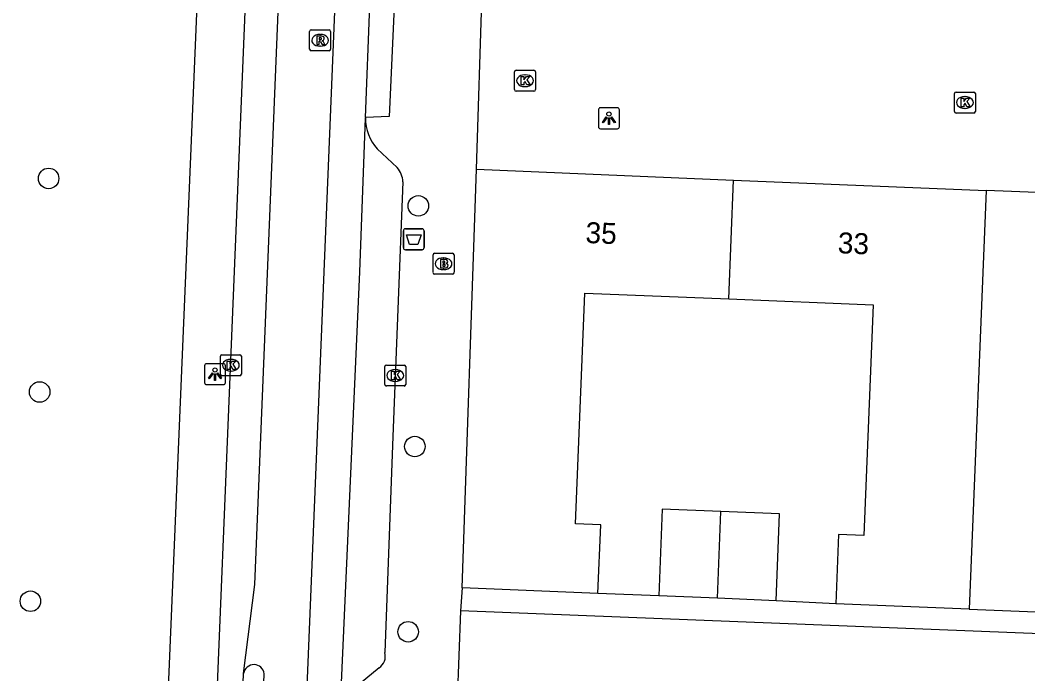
# Model space of a CAD drawing. Extents: x 160787 to 161428, y 386828 to 387483.
# Drawn here: x 161290.73 to 161338.8, y 387141.15 to 387172.31 of the extents above; entities that cross this region are included whole.
import ezdxf

# ---------------------------------------------------------------- set-up
doc = ezdxf.new("R2010")
doc.units = 0
for name, color, linetype in [('IMGEO_Afvalbak', 7, 'Continuous'), ('IMGEO_Boom', 7, 'Continuous'), ('IMGEO_Brandkraan', 7, 'Continuous'), ('IMGEO_Kolk', 7, 'Continuous'), ('IMGEO_Lichtpunt', 7, 'Continuous'), ('IMGEO_Pand', 7, 'Continuous'), ('IMGEO_Pand_nummerreeks', 7, 'Continuous'), ('IMGEO_Rijbaan_lokaal_gesloten', 7, 'Continuous'), ('IMGEO_Rijbaan_lokaal_open', 7, 'Continuous'), ('IMGEO_Rioolput', 7, 'Continuous'), ('IMGEO_Voetpad_open', 7, 'Continuous')]:
    doc.layers.add(name, color=color, linetype=linetype)

msp = doc.modelspace()

# ---------------------------------------------------------------- linework, layer by layer
at = {"layer": 'IMGEO_Afvalbak'}
for p, q in [((161309.114, 387162.368), (161309.904, 387162.368)), ((161309.904, 387162.368), (161309.114, 387162.368)), ((161309.014, 387161.468), (161309.014, 387162.268)), ((161309.014, 387162.268), (161309.014, 387161.468)), ((161310.004, 387162.268), (161310.004, 387161.468)), ((161310.004, 387161.468), (161310.004, 387162.268)), ((161309.904, 387161.368), (161309.114, 387161.368)), ((161309.114, 387161.368), (161309.904, 387161.368))]:
    msp.add_line(p, q, dxfattribs=at)
msp.add_lwpolyline([(161309.157, 387162.082), (161309.861, 387162.082), (161309.712, 387161.612), (161309.306, 387161.612), (161309.157, 387162.082)], dxfattribs=at)
for centre, start, end in [((161309.114, 387162.268), 90, 180), ((161309.114, 387162.268), 90, 180), ((161309.904, 387162.268), 0, 90), ((161309.904, 387162.268), 360, 90), ((161309.114, 387161.468), 180, 270), ((161309.114, 387161.468), 180, 270), ((161309.904, 387161.468), 270, 0), ((161309.904, 387161.468), 270, 0)]:
    msp.add_arc(centre, 0.1, start, end, dxfattribs=at)
at = {"layer": 'IMGEO_Boom'}
for centre in [(161292.092, 387164.766), (161309.728, 387163.458), (161291.664, 387154.586), (161309.563, 387151.986), (161291.224, 387144.609), (161309.243, 387143.153)]:
    msp.add_circle(centre, 0.489, dxfattribs=at)
at = {"layer": 'IMGEO_Brandkraan'}
for p, q in [((161310.43, 387160.274), (161310.43, 387161.126)), ((161310.505, 387161.2), (161311.357, 387161.2)), ((161310.918, 387160.98), (161310.943, 387160.98)), ((161311.431, 387161.126), (161311.431, 387160.274)), ((161310.941, 387160.42), (161310.916, 387160.42)), ((161311.357, 387160.2), (161310.505, 387160.2))]:
    msp.add_line(p, q, dxfattribs=at)
for points in [[(161310.43, 387160.274), (161310.43, 387161.126)], [(161310.505, 387161.2), (161311.357, 387161.2)], [(161310.778, 387160.9), (161310.778, 387160.5), (161310.991, 387160.5)], [(161311.009, 387160.9), (161310.778, 387160.9)], [(161311.431, 387161.126), (161311.431, 387160.274)], [(161310.957, 387160.819), (161310.903, 387160.819), (161310.903, 387160.743)], [(161310.903, 387160.743), (161310.956, 387160.743)], [(161310.965, 387160.667), (161310.903, 387160.667), (161310.903, 387160.586)], [(161310.903, 387160.586), (161310.965, 387160.586)], [(161311.357, 387160.2), (161310.505, 387160.2)]]:
    msp.add_lwpolyline(points, dxfattribs=at)
for centre, radius, start, end in [((161310.507, 387161.124), 0.0765, 91.552, 178.448), ((161310.507, 387161.124), 0.0765, 91.552, 178.448), ((161311.013, 387160.755), 0.145, 59.4692, 91.5367), ((161311.038, 387160.802), 0.0922, 285.5137, 58.1501), ((161311.355, 387161.124), 0.0765, 1.552, 88.448), ((161311.355, 387161.124), 0.0765, 1.552, 88.448), ((161310.958, 387160.781), 0.0379, 267.8285, 90.9355), ((161310.966, 387160.626), 0.0404, 269.8759, 90.5077), ((161310.997, 387160.751), 0.251, 268.6676, 293.5347), ((161311.043, 387160.61), 0.105, 301.3115, 78.989), ((161310.507, 387160.276), 0.0765, 181.552, 268.448), ((161310.507, 387160.276), 0.0765, 181.552, 268.448), ((161311.355, 387160.276), 0.0765, 271.552, 358.448), ((161311.355, 387160.276), 0.0765, 271.552, 358.448)]:
    msp.add_arc(centre, radius, start, end, dxfattribs=at)
for centre, major_axis, ratio, start_param, end_param in [((161310.917, 387160.7), (-0.387, 0.002), 0.722429, 4.712389, 7.853982), ((161310.942, 387160.7), (-0.39, 0.002), 0.717154, 1.570796, 4.712389)]:
    msp.add_ellipse(centre, major_axis=major_axis, ratio=ratio, start_param=start_param, end_param=end_param, dxfattribs=at)
at = {"layer": 'IMGEO_Kolk'}
for p, q in [((161314.316, 387169), (161314.316, 387169.852)), ((161314.391, 387169.926), (161315.243, 387169.926)), ((161314.804, 387169.706), (161314.829, 387169.706)), ((161315.317, 387169.852), (161315.317, 387169)), ((161314.827, 387169.146), (161314.802, 387169.146)), ((161315.243, 387168.926), (161314.391, 387168.926)), ((161335.3, 387167.96), (161335.3, 387168.812)), ((161335.375, 387168.886), (161336.227, 387168.886)), ((161335.788, 387168.666), (161335.813, 387168.666)), ((161336.301, 387168.812), (161336.301, 387167.96)), ((161335.811, 387168.106), (161335.786, 387168.106)), ((161336.227, 387167.886), (161335.375, 387167.886)), ((161300.287, 387155.435), (161300.287, 387156.287)), ((161300.362, 387156.361), (161301.214, 387156.361)), ((161300.775, 387156.141), (161300.8, 387156.141)), ((161301.288, 387156.287), (161301.288, 387155.435)), ((161308.128, 387154.945), (161308.128, 387155.797)), ((161308.203, 387155.871), (161309.055, 387155.871)), ((161308.616, 387155.651), (161308.641, 387155.651)), ((161309.129, 387155.797), (161309.129, 387154.945)), ((161301.214, 387155.361), (161300.362, 387155.361)), ((161300.798, 387155.581), (161300.773, 387155.581)), ((161309.055, 387154.871), (161308.203, 387154.871)), ((161308.639, 387155.091), (161308.614, 387155.091))]:
    msp.add_line(p, q, dxfattribs=at)
for points in [[(161314.316, 387169), (161314.316, 387169.852)], [(161314.391, 387169.926), (161315.243, 387169.926)], [(161314.637, 387169.626), (161314.76, 387169.626), (161314.76, 387169.475), (161314.89, 387169.626), (161315.054, 387169.626), (161314.908, 387169.475), (161315.061, 387169.226), (161314.909, 387169.226), (161314.824, 387169.39), (161314.76, 387169.323), (161314.76, 387169.226), (161314.637, 387169.226), (161314.637, 387169.626)], [(161315.317, 387169.852), (161315.317, 387169)], [(161315.243, 387168.926), (161314.391, 387168.926)], [(161335.3, 387167.96), (161335.3, 387168.812)], [(161335.375, 387168.886), (161336.227, 387168.886)], [(161335.621, 387168.586), (161335.744, 387168.586), (161335.744, 387168.435), (161335.874, 387168.586), (161336.038, 387168.586), (161335.892, 387168.435), (161336.045, 387168.186), (161335.893, 387168.186), (161335.808, 387168.35), (161335.744, 387168.283), (161335.744, 387168.186), (161335.621, 387168.186), (161335.621, 387168.586)], [(161336.301, 387168.812), (161336.301, 387167.96)], [(161336.227, 387167.886), (161335.375, 387167.886)], [(161300.287, 387155.435), (161300.287, 387156.287)], [(161300.362, 387156.361), (161301.214, 387156.361)], [(161301.288, 387156.287), (161301.288, 387155.435)], [(161300.608, 387156.061), (161300.731, 387156.061), (161300.731, 387155.91), (161300.861, 387156.061), (161301.025, 387156.061), (161300.879, 387155.91), (161301.032, 387155.661), (161300.88, 387155.661), (161300.795, 387155.825), (161300.731, 387155.758), (161300.731, 387155.661), (161300.608, 387155.661), (161300.608, 387156.061)], [(161308.128, 387154.945), (161308.128, 387155.797)], [(161308.203, 387155.871), (161309.055, 387155.871)], [(161309.129, 387155.797), (161309.129, 387154.945)], [(161301.214, 387155.361), (161300.362, 387155.361)], [(161308.449, 387155.571), (161308.572, 387155.571), (161308.572, 387155.42), (161308.702, 387155.571), (161308.866, 387155.571), (161308.72, 387155.42), (161308.873, 387155.171), (161308.721, 387155.171), (161308.636, 387155.335), (161308.572, 387155.268), (161308.572, 387155.171), (161308.449, 387155.171), (161308.449, 387155.571)], [(161309.055, 387154.871), (161308.203, 387154.871)]]:
    msp.add_lwpolyline(points, dxfattribs=at)
for centre, start, end in [((161314.393, 387169.85), 91.552, 178.448), ((161314.393, 387169.85), 91.552, 178.448), ((161315.241, 387169.85), 1.552, 88.448), ((161315.241, 387169.85), 1.552, 88.448), ((161314.393, 387169.002), 181.552, 268.448), ((161314.393, 387169.002), 181.552, 268.448), ((161315.241, 387169.002), 271.552, 358.448), ((161315.241, 387169.002), 271.552, 358.448), ((161335.377, 387168.81), 91.552, 178.448), ((161335.377, 387168.81), 91.552, 178.448), ((161336.225, 387168.81), 1.552, 88.448), ((161336.225, 387168.81), 1.552, 88.448), ((161335.377, 387167.962), 181.552, 268.448), ((161335.377, 387167.962), 181.552, 268.448), ((161336.225, 387167.962), 271.552, 358.448), ((161336.225, 387167.962), 271.552, 358.448), ((161300.364, 387156.285), 91.552, 178.448), ((161300.364, 387156.285), 91.552, 178.448), ((161301.212, 387156.285), 1.552, 88.448), ((161301.212, 387156.285), 1.552, 88.448), ((161308.205, 387155.795), 91.552, 178.448), ((161308.205, 387155.795), 91.552, 178.448), ((161309.053, 387155.795), 1.552, 88.448), ((161309.053, 387155.795), 1.552, 88.448), ((161300.364, 387155.437), 181.552, 268.448), ((161300.364, 387155.437), 181.552, 268.448), ((161301.212, 387155.437), 271.552, 358.448), ((161301.212, 387155.437), 271.552, 358.448), ((161308.205, 387154.947), 181.552, 268.448), ((161308.205, 387154.947), 181.552, 268.448), ((161309.053, 387154.947), 271.552, 358.448), ((161309.053, 387154.947), 271.552, 358.448)]:
    msp.add_arc(centre, 0.0765, start, end, dxfattribs=at)
for centre, major_axis, ratio, start_param, end_param in [((161314.803, 387169.426), (-0.387, 0.002), 0.722429, 4.712389, 7.853982), ((161314.828, 387169.426), (-0.39, 0.002), 0.717154, 1.570796, 4.712389), ((161335.787, 387168.386), (-0.387, 0.002), 0.722429, 4.712389, 7.853982), ((161335.812, 387168.386), (-0.39, 0.002), 0.717154, 1.570796, 4.712389), ((161300.774, 387155.861), (-0.387, 0.002), 0.722429, 4.712389, 7.853982), ((161300.799, 387155.861), (-0.39, 0.002), 0.717154, 1.570796, 4.712389), ((161308.615, 387155.371), (-0.387, 0.002), 0.722429, 4.712389, 7.853982), ((161308.64, 387155.371), (-0.39, 0.002), 0.717154, 1.570796, 4.712389)]:
    msp.add_ellipse(centre, major_axis=major_axis, ratio=ratio, start_param=start_param, end_param=end_param, dxfattribs=at)
at = {"layer": 'IMGEO_Lichtpunt'}
for p, q in [((161319.222, 387168.134), (161318.414, 387168.134)), ((161319.222, 387168.134), (161318.414, 387168.134)), ((161318.32, 387168.039), (161318.32, 387167.232)), ((161318.32, 387168.039), (161318.32, 387167.232)), ((161319.316, 387167.232), (161319.316, 387168.039)), ((161319.316, 387167.232), (161319.316, 387168.039)), ((161318.414, 387167.138), (161319.222, 387167.138)), ((161318.414, 387167.138), (161319.222, 387167.138)), ((161299.53, 387155.838), (161299.53, 387155.031)), ((161299.53, 387155.838), (161299.53, 387155.031)), ((161300.432, 387155.933), (161299.624, 387155.933)), ((161300.432, 387155.933), (161299.624, 387155.933)), ((161300.526, 387155.031), (161300.526, 387155.838)), ((161300.526, 387155.031), (161300.526, 387155.838)), ((161299.624, 387154.937), (161300.432, 387154.937)), ((161299.624, 387154.937), (161300.432, 387154.937))]:
    msp.add_line(p, q, dxfattribs=at)
for points in [[(161318.694, 387167.703), (161318.733, 387167.675), (161318.545, 387167.413), (161318.507, 387167.44), (161318.694, 387167.703)], [(161318.796, 387167.655), (161318.843, 387167.655), (161318.843, 387167.333), (161318.796, 387167.333), (161318.796, 387167.655)], [(161318.906, 387167.675), (161318.944, 387167.702), (161319.131, 387167.44), (161319.092, 387167.412), (161318.906, 387167.675)], [(161299.904, 387155.502), (161299.943, 387155.474), (161299.755, 387155.212), (161299.717, 387155.239), (161299.904, 387155.502)], [(161300.006, 387155.454), (161300.053, 387155.454), (161300.053, 387155.132), (161300.006, 387155.132), (161300.006, 387155.454)], [(161300.116, 387155.474), (161300.154, 387155.501), (161300.341, 387155.239), (161300.302, 387155.211), (161300.116, 387155.474)]]:
    msp.add_lwpolyline(points, dxfattribs=at)
for centre in [(161318.819, 387167.837), (161300.029, 387155.636)]:
    msp.add_circle(centre, 0.0994, dxfattribs=at)
for centre, start, end in [((161318.414, 387168.039), 90, 180), ((161318.414, 387168.039), 90, 180), ((161319.222, 387168.039), 0, 90), ((161319.222, 387168.039), 0, 90), ((161318.414, 387167.232), 180, 270), ((161318.414, 387167.232), 180, 270), ((161319.222, 387167.232), 270, 0), ((161319.222, 387167.232), 270, 360), ((161299.624, 387155.838), 90, 180), ((161299.624, 387155.838), 90, 180), ((161300.432, 387155.838), 0, 90), ((161300.432, 387155.838), 0, 90), ((161299.624, 387155.031), 180, 270), ((161299.624, 387155.031), 180, 270), ((161300.432, 387155.031), 270, 0), ((161300.432, 387155.031), 270, 360)]:
    msp.add_arc(centre, 0.0946, start, end, dxfattribs=at)
at = {"layer": 'IMGEO_Pand'}
for points in [[(161311.82, 387145.245), (161312.505, 387165.212)], [(161312.505, 387165.212), (161324.759, 387164.687)], [(161324.545, 387159.022), (161324.759, 387164.687)], [(161324.759, 387164.687), (161336.808, 387164.198)], [(161336.808, 387164.198), (161336, 387144.229)], [(161348.868, 387163.708), (161336.808, 387164.198)], [(161318.294, 387144.982), (161318.427, 387148.25), (161317.218, 387148.3), (161317.665, 387159.301), (161324.545, 387159.022)], [(161324.545, 387159.022), (161331.424, 387158.743), (161330.978, 387147.743), (161329.769, 387147.793), (161329.635, 387144.487)], [(161324.162, 387148.886), (161321.366, 387148.999), (161321.198, 387144.862)], [(161324.006, 387144.748), (161324.162, 387148.886)], [(161326.791, 387144.635), (161326.959, 387148.772), (161324.162, 387148.886)], [(161318.294, 387144.982), (161311.82, 387145.245)], [(161324.006, 387144.748), (161321.198, 387144.862)], [(161326.791, 387144.635), (161324.006, 387144.748)], [(161336, 387144.229), (161329.635, 387144.487)], [(161336, 387144.229), (161342.367, 387143.97)]]:
    msp.add_lwpolyline(points, dxfattribs=at)
at = {"layer": 'IMGEO_Rijbaan_lokaal_gesloten'}
for points in [[(161301.395, 387141.166), (161301.931, 387145.4), (161306.48, 387256.955)], [(161309.144, 387256.108), (161302.568, 387095.562), (161301.538, 387070.326)], [(161298.555, 387102.503), (161299.573, 387126.703), (161302.849, 387206.365)], [(161307.207, 387167.679), (161307.408, 387173.015)], [(161304.494, 387102.119), (161304.742, 387107.036), (161305.983, 387138.943), (161306.935, 387160.321), (161307.207, 387167.643)], [(161307.207, 387167.679), (161307.207, 387167.643)], [(161301.226, 387137.162), (161301.391, 387141.138), (161301.395, 387141.166)], [(161302.226, 387137.162), (161302.38, 387141.148)]]:
    msp.add_lwpolyline(points, dxfattribs=at)
msp.add_arc((161301.886, 387141.09), 0.497, 6.7122, 171.194, dxfattribs=at)
at = {"layer": 'IMGEO_Rijbaan_lokaal_open'}
msp.add_lwpolyline([(161312.505, 387165.212), (161312.774, 387173.707)], dxfattribs=at)
at = {"layer": 'IMGEO_Rioolput'}
for p, q in [((161304.543, 387170.926), (161304.543, 387171.778)), ((161304.618, 387171.852), (161305.47, 387171.852)), ((161305.031, 387171.632), (161305.056, 387171.632)), ((161305.544, 387171.778), (161305.544, 387170.926)), ((161305.054, 387171.072), (161305.029, 387171.072)), ((161305.47, 387170.852), (161304.618, 387170.852))]:
    msp.add_line(p, q, dxfattribs=at)
for points in [[(161304.543, 387170.926), (161304.543, 387171.778)], [(161304.618, 387171.852), (161305.47, 387171.852)], [(161305.132, 387171.55), (161304.88, 387171.552), (161304.88, 387171.152)], [(161305.058, 387171.471), (161305.004, 387171.471), (161305.004, 387171.39)], [(161305.544, 387171.778), (161305.544, 387170.926)], [(161304.88, 387171.152), (161305.004, 387171.152), (161305.004, 387171.314), (161305.015, 387171.314)], [(161305.004, 387171.39), (161305.056, 387171.39)], [(161305.062, 387171.285), (161305.133, 387171.152), (161305.273, 387171.152), (161305.208, 387171.278)], [(161305.47, 387170.852), (161304.618, 387170.852)]]:
    msp.add_lwpolyline(points, dxfattribs=at)
for centre, radius, start, end in [((161304.62, 387171.776), 0.0765, 91.552, 178.448), ((161304.62, 387171.776), 0.0765, 91.552, 178.448), ((161305.064, 387171.375), 0.0964, 77.0061, 93.1865), ((161305.078, 387171.432), 0.0378, 276.6634, 79.6772), ((161305.131, 387171.44), 0.109, 350.3612, 89.416), ((161305.468, 387171.776), 0.0765, 1.552, 88.448), ((161305.468, 387171.776), 0.0765, 1.552, 88.448), ((161305.014, 387171.261), 0.0533, 26.0293, 88.6989), ((161305.04, 387171.579), 0.19, 274.7715, 282.9687), ((161305.129, 387171.44), 0.112, 277.5842, 350.9817), ((161305.113, 387171.225), 0.108, 29.5134, 73.7905), ((161304.62, 387170.928), 0.0765, 181.552, 268.448), ((161304.62, 387170.928), 0.0765, 181.552, 268.448), ((161305.468, 387170.928), 0.0765, 271.552, 358.448), ((161305.468, 387170.928), 0.0765, 271.552, 358.448)]:
    msp.add_arc(centre, radius, start, end, dxfattribs=at)
for centre, major_axis, ratio, start_param, end_param in [((161305.03, 387171.352), (-0.387, 0.002), 0.722429, 4.712389, 7.853982), ((161305.055, 387171.352), (-0.39, 0.002), 0.717154, 1.570796, 4.712389)]:
    msp.add_ellipse(centre, major_axis=major_axis, ratio=ratio, start_param=start_param, end_param=end_param, dxfattribs=at)
at = {"layer": 'IMGEO_Voetpad_open'}
for points in [[(161299.307, 387176.427), (161296.512, 387109.859)], [(161307.408, 387173.015), (161308.576, 387172.951), (161308.334, 387167.724), (161307.207, 387167.679)], [(161307.763, 387166.18), (161308.719, 387165.287)], [(161308.99, 387164.601), (161308.518, 387152.461), (161308.125, 387142.158)], [(161311.82, 387145.245), (161311.739, 387144.153)], [(161321.198, 387144.862), (161318.294, 387144.982)], [(161329.635, 387144.487), (161326.791, 387144.635)], [(161311.739, 387144.153), (161311.343, 387133.51)], [(161377.587, 387142.566), (161377.49, 387141.542), (161311.739, 387144.153)], [(161307.853, 387141.436), (161306.594, 387140.392)]]:
    msp.add_lwpolyline(points, dxfattribs=at)
for centre, radius, start, end in [((161309.39, 387167.636), 2.183, 179.8041, 221.8136), ((161307.862, 387164.552), 1.129, 2.4916, 40.6208), ((161307.512, 387141.977), 0.64, 302.2576, 16.4564)]:
    msp.add_arc(centre, radius, start, end, dxfattribs=at)

# ---------------------------------------------------------------- texts
at = {"layer": 'IMGEO_Pand_nummerreeks'}
for s, p in [('35', (161317.687, 387161.692)), ('33', (161329.721, 387161.203))]:
    msp.add_text(s, height=1, rotation=357.6746, dxfattribs=at).set_placement(p)

doc.saveas('drawing.dxf')
